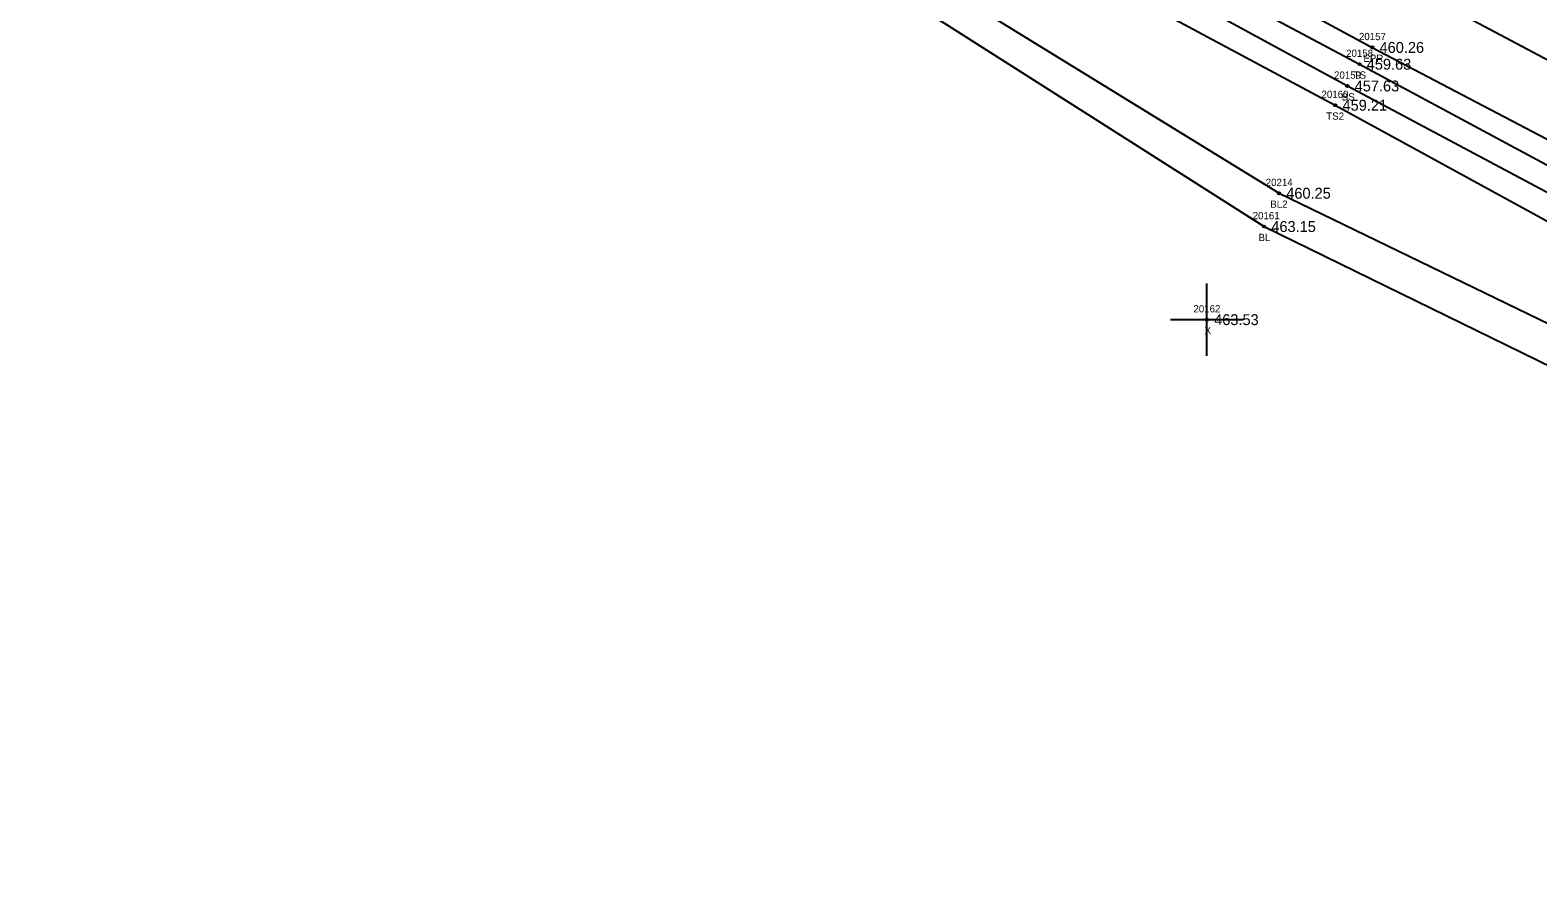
# Model space of a CAD drawing. Extents: x 1810114 to 1811498, y 790790 to 791824.
# Drawn here: x 1810130.3 to 1810337.9, y 791409.1 to 791524.2 of the extents above; entities that cross this region are included whole.
import ezdxf

# ---------------------------------------------------------------- set-up
doc = ezdxf.new("R2010")
doc.units = 0
for name, color, linetype in [('RD_DTM_BkLn1', 7, 'Continuous'), ('RD_DTM_BkLn2', 7, 'Continuous'), ('RD_DTM_BkLn_txCode', 7, 'Continuous'), ('RD_EX_Misc', 7, 'Continuous'), ('RD_EX_Misc_txCode', 7, 'Continuous'), ('RD_EX_Road', 7, 'Continuous'), ('RD_EX_Road_txCode', 7, 'Continuous'), ('RD_EX_TX_Misc_ELEV', 7, 'Continuous'), ('RD_EX_TX_Road_ELEV', 7, 'Continuous'), ('RD_SMD_Locator', 7, 'Continuous')]:
    doc.layers.add(name, color=color, linetype=linetype)

msp = doc.modelspace()

# ---------------------------------------------------------------- linework, layer by layer
at = {"layer": 'RD_DTM_BkLn1'}
for points in [[(1810142.92, 791624.85), (1810231.36, 791577.96), (1810319.85, 791530.5), (1810408.61, 791483.38), (1810496.8, 791436.85), (1810585.08, 791388.93), (1810674.47, 791342.37), (1810763.64, 791295.68)], [(1810130.25, 791598.81), (1810215.39, 791551.2), (1810300.2, 791497.21), (1810392.2, 791452.25), (1810484.95, 791413.19)], [(1810144.18, 791597.3), (1810217.47, 791553.92), (1810302.26, 791501.79), (1810394.73, 791457), (1810484.95, 791413.19)]]:
    msp.add_lwpolyline(points, dxfattribs=at)
at = {"layer": 'RD_DTM_BkLn2'}
for points in [[(1810136.46, 791613.23), (1810225.09, 791566.55), (1810313.34, 791519.56), (1810402.58, 791471.61), (1810490.03, 791423.34), (1810516.06, 791407.46), (1810541.24, 791393.02), (1810575.56, 791368.65), (1810662.82, 791320.73), (1810730.85, 791285.33), (1810742.82, 791282.19), (1810752.34, 791280.87), (1810757.12, 791283.77)], [(1810135.37, 791610.75), (1810224.14, 791564.21), (1810311.68, 791516.56), (1810401.2, 791468.88), (1810488.81, 791421.27), (1810514.98, 791405.31), (1810539.89, 791390.39), (1810572.74, 791363.8), (1810659.47, 791316.31), (1810726.51, 791276.73), (1810738.6, 791270.6), (1810748.52, 791266.73), (1810763.99, 791268.4)], [(1810133.65, 791608.34), (1810222.15, 791560.96), (1810310.01, 791513.91), (1810399.26, 791465.14), (1810487.96, 791419.17), (1810513.17, 791403.16), (1810538.21, 791387.66)]]:
    msp.add_lwpolyline(points, dxfattribs=at)
at = {"layer": 'RD_EX_Misc'}
for p, q in [((1810292.33, 791479.39), (1810292.33, 791489.39)), ((1810287.33, 791484.39), (1810297.33, 791484.39))]:
    msp.add_line(p, q, dxfattribs=at)
at = {"layer": 'RD_EX_Road'}
msp.add_lwpolyline([(1810138.18, 791616.8), (1810226.92, 791569.59), (1810315.11, 791521.87), (1810404.37, 791475.11), (1810492.73, 791428.56), (1810580.86, 791380.55), (1810670.21, 791334.43), (1810759.54, 791287.61)], dxfattribs=at)
at = {"layer": 'RD_SMD_Locator'}
for centre in [(1810315.11, 791521.87), (1810313.34, 791519.56), (1810311.68, 791516.56), (1810310.01, 791513.91), (1810302.26, 791501.79), (1810300.2, 791497.21), (1810292.33, 791484.39)]:
    msp.add_circle(centre, 0.15, dxfattribs=at)

# ---------------------------------------------------------------- texts
at = {"layer": 'RD_DTM_BkLn_txCode'}
for s, p in [('20158', (1810311.5, 791520.56)), ('20159', (1810309.84, 791517.56)), ('TS', (1810312.54, 791517.56)), ('20160', (1810308.11, 791514.91)), ('BS', (1810310.9, 791514.56)), ('TS2', (1810308.77, 791511.91)), ('20214', (1810300.43, 791502.79)), ('BL2', (1810301.06, 791499.79)), ('20161', (1810298.63, 791498.21)), ('BL', (1810299.44, 791495.21))]:
    msp.add_text(s, height=1, dxfattribs=at).set_placement(p)
at = {"layer": 'RD_EX_Misc_txCode'}
for s, p in [('20162', (1810290.47, 791485.39)), ('X', (1810292.01, 791482.39))]:
    msp.add_text(s, height=1, dxfattribs=at).set_placement(p)
at = {"layer": 'RD_EX_Road_txCode'}
for s, p in [('20157', (1810313.27, 791522.87)), ('EPR', (1810313.88, 791519.87))]:
    msp.add_text(s, height=1, dxfattribs=at).set_placement(p)
at = {"layer": 'RD_EX_TX_Misc_ELEV'}
for s, p in [('459.63', (1810314.34, 791518.81)), ('457.63', (1810312.68, 791515.81)), ('459.21', (1810311.01, 791513.16)), ('460.25', (1810303.26, 791501.04)), ('463.15', (1810301.2, 791496.46)), ('463.53', (1810293.33, 791483.64))]:
    msp.add_text(s, height=1.5, dxfattribs=at).set_placement(p)
at = {"layer": 'RD_EX_TX_Road_ELEV'}
msp.add_text('460.26', height=1.5, dxfattribs=at).set_placement((1810316.11, 791521.12))

doc.saveas('drawing.dxf')
